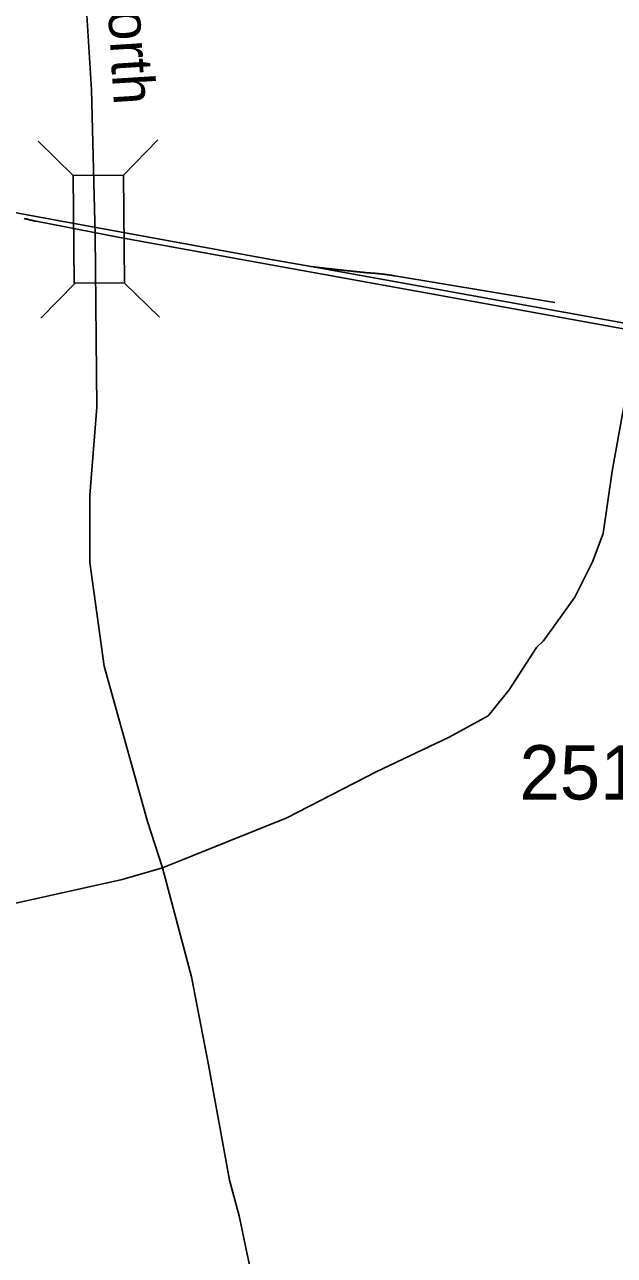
# Model space of a CAD drawing. Extents: x 1364363 to 1407445, y 538563 to 573342.
# Drawn here: x 1390128 to 1391486, y 547242 to 550075 of the extents above; entities that cross this region are included whole.
import ezdxf

# ---------------------------------------------------------------- set-up
doc = ezdxf.new("R2010")
doc.units = 0
for name, color, linetype in [('Exist Railroad Mainline', 7, 'Continuous'), ('Exist Railroad Siding', 7, 'Continuous'), ('Exist Railroad Spur', 7, 'Continuous'), ('Exist Road Secondary Structure Standard Bridge CELL', 7, 'Continuous'), ('Exist Road Secondary Type 51 Attributed', 7, 'Continuous'), ('Exist Road Secondary Type 51 Label', 7, 'Continuous'), ('Exist Road Secondary Type 51 Number Label', 7, 'Continuous')]:
    doc.layers.add(name, color=color, linetype=linetype)

msp = doc.modelspace()

# ---------------------------------------------------------------- linework, layer by layer
at = {"layer": 'Exist Railroad Mainline'}
for points in [[(1390154.1, 549622.6), (1390152.8, 549622.9), (1390151.2, 549623.2), (1390149.9, 549623.6), (1390148.3, 549623.9), (1390147, 549624.3), (1390145.5, 549624.6), (1390144.1, 549624.9), (1390142.6, 549625.2), (1390141.3, 549625.6), (1390139.7, 549626), (1390138.4, 549626.3), (1390136.9, 549626.6), (1390135.5, 549626.9), (1390134, 549627.3), (1390132.7, 549627.6), (1390131.1, 549628), (1390129.8, 549628.3), (1390128.2, 549628.7), (1390126.9, 549629)], [(1391599.7, 549358.3), (1391119.4, 549445.4), (1390346.6, 549585.1), (1390154.1, 549622.6)]]:
    msp.add_lwpolyline(points, dxfattribs=at)
at = {"layer": 'Exist Railroad Siding'}
for points in [[(1390012.4, 549659.5), (1390204.4, 549624.5), (1390699, 549533.9), (1390792.1, 549517.7)], [(1390792.1, 549517.7), (1391441.4, 549400.6), (1392320.9, 549241.1), (1392752.5, 549162.8), (1393053.7, 549108.7)]]:
    msp.add_lwpolyline(points, dxfattribs=at)
at = {"layer": 'Exist Railroad Spur'}
msp.add_line((1390980.1, 549497.1), (1391348.7, 549436), dxfattribs=at)
for points in [[(1390792.1, 549517.7), (1390793.3, 549517.5), (1390794.7, 549517.4), (1390796, 549517.2), (1390797.2, 549517.1), (1390798.5, 549516.9), (1390799.8, 549516.8), (1390801.1, 549516.7), (1390802.4, 549516.5), (1390803.6, 549516.4), (1390805, 549516.2), (1390806.3, 549516.1), (1390807.5, 549516), (1390808.9, 549515.7), (1390810.1, 549515.6), (1390811.4, 549515.4), (1390812.6, 549515.3), (1390814, 549515.2), (1390815.3, 549515), (1390816.5, 549514.9), (1390817.8, 549514.8), (1390819.2, 549514.6), (1390820.4, 549514.4), (1390821.6, 549514.3), (1390823, 549514.1), (1390824.3, 549514), (1390825.5, 549513.9), (1390826.9, 549513.7), (1390828.1, 549513.5), (1390829.4, 549513.4), (1390830.8, 549513.2), (1390832, 549513.1), (1390833.2, 549513), (1390834.6, 549512.9), (1390835.9, 549512.7), (1390837.1, 549512.6), (1390838.3, 549512.4), (1390839.8, 549512.3), (1390841, 549512.1), (1390842.2, 549512), (1390843.7, 549511.9), (1390844.9, 549511.7), (1390846.1, 549511.5), (1390847.4, 549511.4), (1390848.7, 549511.3), (1390850, 549511.1), (1390851.3, 549511), (1390852.6, 549510.9), (1390853.8, 549510.8), (1390855.2, 549510.6), (1390856.5, 549510.4), (1390857.7, 549510.3), (1390859, 549510.2), (1390860.3, 549510), (1390861.6, 549509.9), (1390862.8, 549509.7), (1390864.1, 549509.6), (1390865.5, 549509.5), (1390866.7, 549509.3), (1390868, 549509.2), (1390869.4, 549509.1), (1390870.6, 549508.9), (1390871.9, 549508.8), (1390873.1, 549508.7), (1390874.5, 549508.5), (1390875.8, 549508.4), (1390877, 549508.3), (1390878.3, 549508.1), (1390879.7, 549508), (1390880.9, 549507.9), (1390882.2, 549507.7), (1390883.5, 549507.5), (1390884.8, 549507.4), (1390886.1, 549507.3), (1390887.4, 549507.2), (1390888.6, 549507.1), (1390889.9, 549506.9), (1390891.2, 549506.8), (1390892.5, 549506.6), (1390893.7, 549506.5), (1390895.1, 549506.4), (1390896.4, 549506.3), (1390897.6, 549506.1), (1390899, 549506), (1390900.3, 549505.9), (1390901.5, 549505.7), (1390902.8, 549505.6), (1390904.2, 549505.5), (1390905.4, 549505.3), (1390906.6, 549505.2), (1390908, 549505.1), (1390909.3, 549504.9), (1390910.5, 549504.8), (1390911.9, 549504.7), (1390913.1, 549504.6), (1390914.4, 549504.4), (1390915.8, 549504.3), (1390917, 549504.2), (1390918.2, 549504.1), (1390919.6, 549504)], [(1390919.6, 549504), (1390920.2, 549503.9), (1390920.8, 549503.9), (1390921.4, 549503.8), (1390922, 549503.8), (1390922.6, 549503.8), (1390923.2, 549503.7), (1390923.9, 549503.7), (1390924.5, 549503.6), (1390925.1, 549503.6), (1390925.8, 549503.5), (1390926.4, 549503.5), (1390927, 549503.5), (1390927.5, 549503.4), (1390928.2, 549503.4), (1390928.8, 549503.4), (1390929.4, 549503.3), (1390930, 549503.2), (1390930.6, 549503.2), (1390931.2, 549503.2), (1390931.8, 549503.1), (1390932.5, 549503.1), (1390933.1, 549503), (1390933.8, 549502.9), (1390934.4, 549502.9), (1390934.9, 549502.9), (1390935.5, 549502.8), (1390936.2, 549502.7), (1390936.8, 549502.7), (1390937.4, 549502.6), (1390938, 549502.6), (1390938.6, 549502.6), (1390939.2, 549502.5), (1390939.8, 549502.4), (1390940.5, 549502.4), (1390941.1, 549502.3), (1390941.6, 549502.3), (1390942.2, 549502.2), (1390942.9, 549502.1), (1390943.5, 549502.1), (1390944.2, 549502), (1390944.8, 549502), (1390945.4, 549501.9), (1390946, 549501.8), (1390946.6, 549501.8), (1390947.2, 549501.7), (1390947.7, 549501.6), (1390948.4, 549501.5), (1390949, 549501.5), (1390949.6, 549501.4), (1390950.2, 549501.3), (1390950.9, 549501.2), (1390951.5, 549501.2), (1390952.1, 549501.1), (1390952.8, 549501.1), (1390953.3, 549501), (1390953.9, 549500.9), (1390954.5, 549500.8), (1390955.1, 549500.7), (1390955.7, 549500.7), (1390956.4, 549500.6), (1390957, 549500.5), (1390957.6, 549500.4), (1390958.3, 549500.4), (1390958.7, 549500.3), (1390959.3, 549500.2), (1390960, 549500.1), (1390960.7, 549500.1), (1390961.3, 549500), (1390961.9, 549499.9), (1390962.5, 549499.8), (1390963.1, 549499.7), (1390963.7, 549499.6), (1390964.2, 549499.5), (1390964.9, 549499.4), (1390965.5, 549499.4), (1390966.1, 549499.2), (1390966.7, 549499.2), (1390967.4, 549499.1), (1390968, 549499), (1390968.7, 549498.9), (1390969.2, 549498.8), (1390969.8, 549498.7), (1390970.4, 549498.6), (1390971, 549498.6), (1390971.6, 549498.4), (1390972.2, 549498.4), (1390972.9, 549498.3), (1390973.4, 549498.2), (1390974, 549498.1), (1390974.6, 549498), (1390975.2, 549497.9), (1390975.8, 549497.8), (1390976.5, 549497.7), (1390977.2, 549497.5), (1390977.6, 549497.4), (1390978.3, 549497.4), (1390978.9, 549497.2), (1390979.5, 549497.1), (1390980.1, 549497.1)]]:
    msp.add_lwpolyline(points, dxfattribs=at)
at = {"layer": 'Exist Road Secondary Structure Standard Bridge CELL'}
for p, q in [((1390158.7, 549807.2), (1390239.6, 549728)), ((1390434.6, 549809.9), (1390355.3, 549729.1)), ((1390244, 549480.1), (1390164.8, 549399.3)), ((1390357.2, 549481.2), (1390438, 549402))]:
    msp.add_line(p, q, dxfattribs=at)
msp.add_lwpolyline([(1390355.3, 549729.1), (1390357.7, 549481.2), (1390242, 549480.1), (1390239.6, 549728)], close=True, dxfattribs=at)
at = {"layer": 'Exist Road Secondary Type 51 Attributed'}
for points in [[(1390279.8, 552513.5), (1390301.6, 552254), (1390309.8, 552131.7), (1390315.9, 551705.2), (1390293.5, 551087.1), (1390284.2, 550788), (1390278.7, 550738.1), (1390270.4, 550444.4), (1390269, 550198.6), (1390270.4, 550109.2), (1390281.8, 549925.5), (1390290.5, 549590.6)], [(1390290.5, 549590.6), (1390294.3, 549194.5), (1390277.8, 548992), (1390277.8, 548837.3), (1390310.7, 548598.3), (1390377.5, 548359.4), (1390410.4, 548241.1), (1390445.5, 548134.1)], [(1390445.5, 548134.1), (1390731.2, 548249.2), (1390937.5, 548355.1), (1391105.2, 548435.3), (1391194.8, 548484.2), (1391243.7, 548544), (1391306.3, 548641.6), (1391322.5, 548656.7), (1391394.5, 548757.3), (1391435.3, 548838.8), (1391459.7, 548904), (1391480.5, 549047.8), (1391540.9, 549383.7)], [(1389188.8, 547747.4), (1389280.7, 547825.3), (1389350.2, 547869.3), (1389395.1, 547886.8), (1389423.4, 547900.4), (1389463.7, 547913.4), (1389748.7, 547978.3), (1389927.1, 548013), (1390352.2, 548107.2), (1390445.5, 548134.1)], [(1390445.5, 548134.1), (1390511.6, 547883.7), (1390551.3, 547680.8), (1390599.8, 547415.7), (1390622.1, 547333.2), (1390640.4, 547244.8), (1390682.3, 547051.9), (1390760.4, 546680.7), (1390782.6, 546603.1)]]:
    msp.add_lwpolyline(points, dxfattribs=at)

# ---------------------------------------------------------------- texts
at = {"layer": 'Exist Road Secondary Type 51 Label'}
msp.add_text('North', height=95, rotation=273.554, dxfattribs=at).set_placement((1390314.1, 550199))
at = {"layer": 'Exist Road Secondary Type 51 Number Label'}
msp.add_text('2519', height=125, dxfattribs=at).set_placement((1391267.2, 548291.7))

doc.saveas('drawing.dxf')
